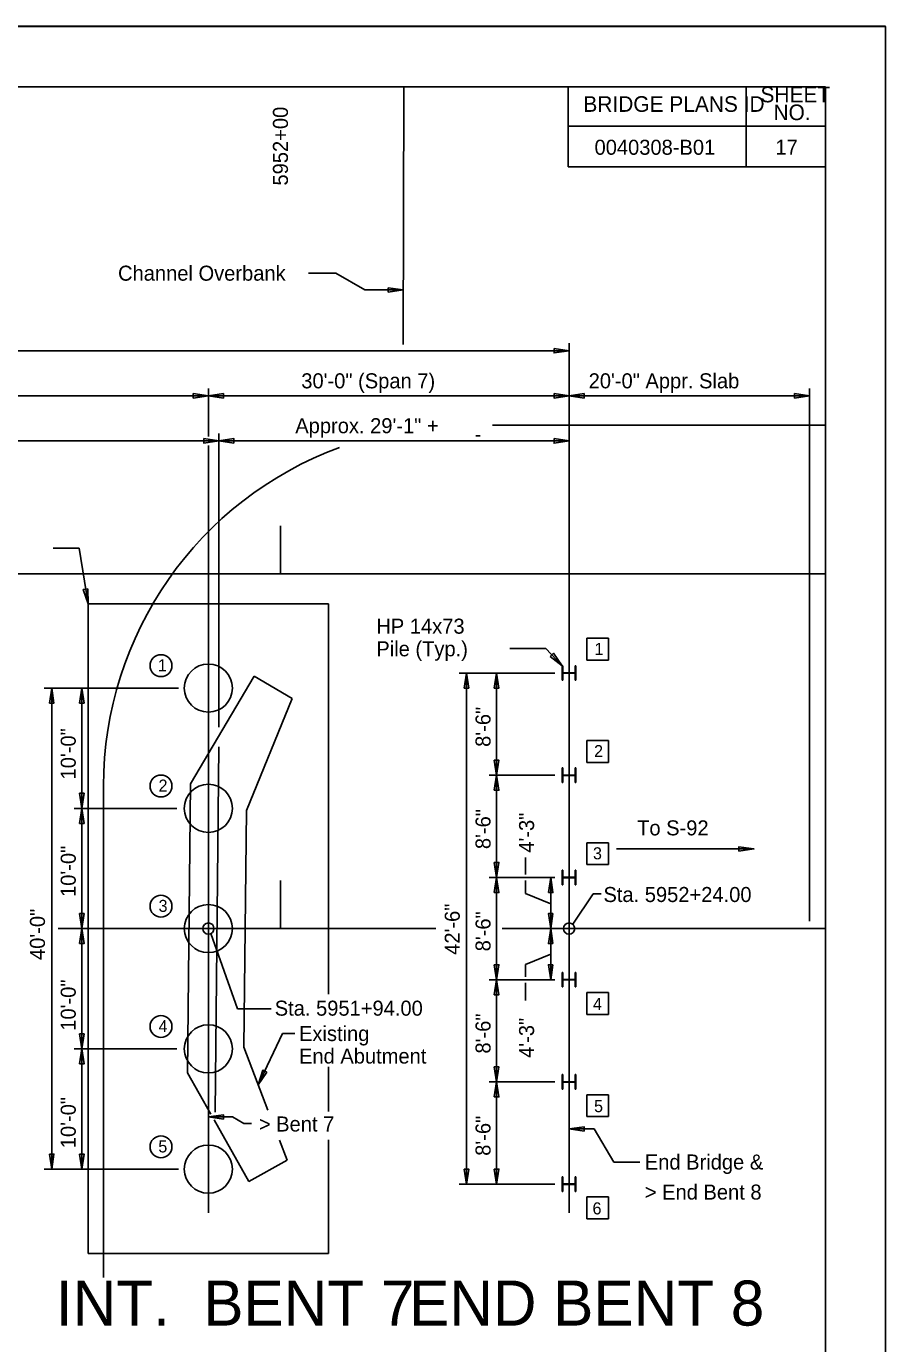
# Model space of a CAD drawing. Extents: x -10371 to -10009, y 1939 to 2167.
# Drawn here: x -10082 to -10010.6, y 2050 to 2159.5 of the extents above; entities that cross this region are included whole.
import ezdxf

# ---------------------------------------------------------------- set-up
doc = ezdxf.new("R2010")
doc.units = 0
for name, color, linetype in [('BR_AUTO DIMENSION', 7, 'Continuous'), ('BR_BORDER LINES', 7, 'Continuous'), ('BR_CENTER LINES', 7, 'Continuous'), ('BR_CONCRETE', 7, 'Continuous'), ('BR_GROUND LINES', 7, 'Continuous'), ('BR_STRUCTURAL STEEL', 7, 'Continuous'), ('BR_TABLE LINES', 7, 'Continuous'), ('BR_TEXT', 7, 'Continuous'), ('RD_SHT_IplotShp', 7, 'Continuous')]:
    doc.layers.add(name, color=color, linetype=linetype)

# ---------------------------------------------------------------- blocks, each defined once
blk = doc.blocks.new('B')
at = {"layer": 'BR_AUTO DIMENSION'}
blk.add_lwpolyline([(-0.2, 0.03), (0, 0), (-0.2, -0.03)], close=True, dxfattribs=at)
blk = doc.blocks.new('ARROW')
at = {"layer": 'BR_AUTO DIMENSION', "xscale": 0.625, "yscale": 0.625}
blk.add_blockref('B', (0, 0), dxfattribs=at)

msp = doc.modelspace()

# ---------------------------------------------------------------- linework, layer by layer
at = {"layer": 'BR_AUTO DIMENSION'}
for p, q in [((-10056.31, 2138.99), (-10058.58, 2138.99)), ((-10053.9, 2137.6), (-10056.31, 2138.99)), ((-10050.7, 2137.6), (-10053.9, 2137.6)), ((-10330.91, 2132.54), (-10036.91, 2132.54)), ((-10016.91, 2085.12), (-10016.91, 2129.41)), ((-10350.91, 2128.79), (-10016.91, 2128.79)), ((-10330.91, 2125.04), (-10036.91, 2125.04)), ((-10079.81, 2116.13), (-10077.66, 2116.13)), ((-10076.91, 2111.49), (-10077.66, 2116.13)), ((-10038.84, 2107.79), (-10041.84, 2107.79)), ((-10037.48, 2106.35), (-10038.84, 2107.79)), ((-10038.1, 2105.74), (-10046.06, 2105.74)), ((-10045.44, 2105.74), (-10045.44, 2063.24)), ((-10042.94, 2105.74), (-10042.94, 2105.74)), ((-10042.94, 2105.74), (-10042.94, 2063.24)), ((-10069.4, 2104.49), (-10080.56, 2104.49)), ((-10079.94, 2104.49), (-10079.94, 2064.49)), ((-10077.44, 2104.49), (-10077.44, 2104.49)), ((-10077.44, 2104.49), (-10077.44, 2064.49)), ((-10038.1, 2097.24), (-10043.56, 2097.24)), ((-10069.54, 2094.49), (-10078.06, 2094.49)), ((-10021.54, 2091.11), (-10032.97, 2091.11)), ((-10040.54, 2090.41), (-10040.54, 2088.99)), ((-10038.1, 2088.74), (-10043.56, 2088.74)), ((-10038.44, 2088.74), (-10038.44, 2080.24)), ((-10040.54, 2088.49), (-10040.54, 2087.41)), ((-10040.54, 2087.41), (-10038.44, 2086.54)), ((-10066.7, 2084.07), (-10064.48, 2077.83)), ((-10040.54, 2081.51), (-10038.44, 2082.37)), ((-10040.54, 2081.51), (-10040.54, 2080.49)), ((-10038.1, 2080.24), (-10043.56, 2080.24)), ((-10040.54, 2079.99), (-10040.54, 2078.5)), ((-10064.48, 2077.83), (-10061.69, 2077.83)), ((-10062.76, 2071.51), (-10060.73, 2075.76)), ((-10060.73, 2075.76), (-10059.71, 2075.76)), ((-10069.54, 2074.49), (-10078.06, 2074.49)), ((-10038.1, 2071.74), (-10043.56, 2071.74)), ((-10066.91, 2068.83), (-10064.91, 2068.83)), ((-10064.91, 2068.83), (-10063.97, 2068.29)), ((-10063.97, 2068.29), (-10063.32, 2068.29)), ((-10036.91, 2067.83), (-10034.81, 2067.83)), ((-10034.81, 2067.83), (-10033.19, 2065.08)), ((-10033.19, 2065.08), (-10031.03, 2065.08)), ((-10069.4, 2064.49), (-10080.56, 2064.49)), ((-10077.44, 2064.49), (-10077.44, 2064.49)), ((-10038.1, 2063.24), (-10046.06, 2063.24)), ((-10042.94, 2063.24), (-10042.94, 2063.24))]:
    msp.add_line(p, q, dxfattribs=at)
for points in [[(-10051.95, 2137.78), (-10050.7, 2137.6), (-10051.95, 2137.41)], [(-10038.16, 2132.73), (-10036.91, 2132.54), (-10038.16, 2132.35)], [(-10068.16, 2128.98), (-10066.91, 2128.79), (-10068.16, 2128.6)], [(-10065.66, 2128.6), (-10066.91, 2128.79), (-10065.66, 2128.98)], [(-10038.16, 2128.98), (-10036.91, 2128.79), (-10038.16, 2128.6)], [(-10035.66, 2128.6), (-10036.91, 2128.79), (-10035.66, 2128.98)], [(-10018.16, 2128.98), (-10016.91, 2128.79), (-10018.16, 2128.6)], [(-10067.28, 2125.23), (-10066.03, 2125.04), (-10067.28, 2124.85)], [(-10064.78, 2124.85), (-10066.03, 2125.04), (-10064.78, 2125.23)], [(-10038.16, 2125.23), (-10036.91, 2125.04), (-10038.16, 2124.85)], [(-10038.48, 2107.12), (-10037.48, 2106.35), (-10038.21, 2107.38)], [(-10045.63, 2104.49), (-10045.44, 2105.74), (-10045.25, 2104.49)], [(-10043.13, 2104.49), (-10042.94, 2105.74), (-10042.75, 2104.49)], [(-10080.13, 2103.24), (-10079.94, 2104.49), (-10079.75, 2103.24)], [(-10077.63, 2103.24), (-10077.44, 2104.49), (-10077.25, 2103.24)], [(-10043.13, 2098.49), (-10042.94, 2097.24), (-10042.75, 2098.49)], [(-10043.13, 2095.99), (-10042.94, 2097.24), (-10042.75, 2095.99)], [(-10077.63, 2095.74), (-10077.44, 2094.49), (-10077.25, 2095.74)], [(-10077.63, 2093.24), (-10077.44, 2094.49), (-10077.25, 2093.24)], [(-10022.79, 2090.92), (-10021.54, 2091.11), (-10022.79, 2091.3)], [(-10043.13, 2089.99), (-10042.94, 2088.74), (-10042.75, 2089.99)], [(-10043.13, 2087.49), (-10042.94, 2088.74), (-10042.75, 2087.49)], [(-10038.63, 2087.49), (-10038.44, 2088.74), (-10038.25, 2087.49)], [(-10077.63, 2085.74), (-10077.44, 2084.49), (-10077.25, 2085.74)], [(-10038.25, 2085.74), (-10038.44, 2084.49), (-10038.63, 2085.74)], [(-10077.63, 2083.24), (-10077.44, 2084.49), (-10077.25, 2083.24)], [(-10038.25, 2083.24), (-10038.44, 2084.49), (-10038.63, 2083.24)], [(-10043.13, 2081.49), (-10042.94, 2080.24), (-10042.75, 2081.49)], [(-10038.25, 2081.49), (-10038.44, 2080.24), (-10038.63, 2081.49)], [(-10043.13, 2078.99), (-10042.94, 2080.24), (-10042.75, 2078.99)], [(-10077.63, 2075.74), (-10077.44, 2074.49), (-10077.25, 2075.74)], [(-10077.63, 2073.24), (-10077.44, 2074.49), (-10077.25, 2073.24)], [(-10062.04, 2072.55), (-10062.76, 2071.51), (-10062.38, 2072.71)], [(-10043.13, 2072.99), (-10042.94, 2071.74), (-10042.75, 2072.99)], [(-10043.13, 2070.49), (-10042.94, 2071.74), (-10042.75, 2070.49)], [(-10065.66, 2068.65), (-10066.91, 2068.83), (-10065.66, 2069.02)], [(-10035.66, 2067.65), (-10036.91, 2067.83), (-10035.66, 2068.02)], [(-10080.13, 2065.74), (-10079.94, 2064.49), (-10079.75, 2065.74)], [(-10077.63, 2065.74), (-10077.44, 2064.49), (-10077.25, 2065.74)], [(-10045.63, 2064.49), (-10045.44, 2063.24), (-10045.25, 2064.49)], [(-10043.13, 2064.49), (-10042.94, 2063.24), (-10042.75, 2064.49)]]:
    msp.add_lwpolyline(points, close=True, dxfattribs=at)
msp.add_lwpolyline([(-10036.6, 2084.85), (-10034.9, 2087.38), (-10034.25, 2087.38)], dxfattribs=at)
for centre in [(-10066.91, 2084.49), (-10036.91, 2084.49)]:
    msp.add_circle(centre, 0.469, dxfattribs=at)
at = {"layer": 'BR_BORDER LINES'}
for p, q in [((-10370.58, 2159.51), (-10010.58, 2159.51)), ((-10015.58, 2154.49), (-10352.25, 2154.49)), ((-10036.98, 2147.83), (-10036.98, 2154.49)), ((-10023.92, 2154.49), (-10023.92, 2154.49)), ((-10022.18, 2147.83), (-10022.18, 2154.49)), ((-10019.76, 2154.49), (-10019.76, 2154.49)), ((-10015.58, 1944.49), (-10015.58, 2154.49)), ((-10036.98, 2151.2), (-10015.58, 2151.2)), ((-10015.58, 2147.83), (-10036.98, 2147.83))]:
    msp.add_line(p, q, dxfattribs=at)
at = {"layer": 'BR_CENTER LINES'}
for p, q in [((-10036.91, 2060.87), (-10036.91, 2133.16)), ((-10066.91, 2125.41), (-10066.91, 2129.41)), ((-10066.91, 2060.87), (-10066.91, 2124.66)), ((-10060.91, 2113.99), (-10060.91, 2117.99)), ((-10352.25, 2113.99), (-10015.58, 2113.99)), ((-10060.91, 2084.49), (-10060.91, 2088.49)), ((-10079.4, 2084.49), (-10047.99, 2084.49)), ((-10042.48, 2084.49), (-10015.58, 2084.49))]:
    msp.add_line(p, q, dxfattribs=at)
at = {"layer": 'BR_CONCRETE'}
for p, q in [((-10068.39, 2096.54), (-10063.1, 2105.48)), ((-10059.95, 2103.61), (-10063.1, 2105.48)), ((-10063.75, 2094.3), (-10059.95, 2103.61)), ((-10068.39, 2096.54), (-10068.65, 2072.5)), ((-10063.75, 2094.3), (-10063.96, 2074.64)), ((-10063.96, 2074.64), (-10061.95, 2069.4)), ((-10068.65, 2072.5), (-10066.71, 2069.05)), ((-10066.44, 2068.58), (-10063.55, 2063.45)), ((-10060.99, 2066.9), (-10060.35, 2065.24)), ((-10060.35, 2065.24), (-10063.55, 2063.45))]:
    msp.add_line(p, q, dxfattribs=at)
for centre in [(-10066.91, 2104.49), (-10066.91, 2094.49), (-10066.91, 2084.49), (-10066.91, 2074.49), (-10066.91, 2064.49)]:
    msp.add_circle(centre, 2, dxfattribs=at)
at = {"layer": 'BR_GROUND LINES'}
for p, q in [((-10043.29, 2126.35), (-10015.58, 2126.35)), ((-10075.63, 2096.35), (-10075.63, 2055.47))]:
    msp.add_line(p, q, dxfattribs=at)
msp.add_arc((-10045.63, 2096.35), 30, 110.2124, 180, dxfattribs=at)
at = {"layer": 'BR_STRUCTURAL STEEL'}
for p, q in [((-10037.48, 2105.14), (-10037.48, 2106.35)), ((-10037.48, 2106.35), (-10037.44, 2106.35)), ((-10037.44, 2106.35), (-10037.44, 2105.82)), ((-10036.39, 2105.82), (-10036.39, 2106.35)), ((-10036.39, 2106.35), (-10036.34, 2106.35)), ((-10036.34, 2106.35), (-10036.34, 2105.14)), ((-10037.44, 2105.14), (-10037.48, 2105.14)), ((-10037.44, 2105.67), (-10037.44, 2105.14)), ((-10037.38, 2105.76), (-10036.44, 2105.76)), ((-10036.44, 2105.72), (-10037.38, 2105.72)), ((-10036.39, 2105.14), (-10036.39, 2105.67)), ((-10036.34, 2105.14), (-10036.39, 2105.14)), ((-10037.48, 2096.64), (-10037.48, 2097.85)), ((-10037.48, 2097.85), (-10037.44, 2097.85)), ((-10037.44, 2097.85), (-10037.44, 2097.32)), ((-10036.39, 2097.32), (-10036.39, 2097.85)), ((-10036.39, 2097.85), (-10036.34, 2097.85)), ((-10036.34, 2097.85), (-10036.34, 2096.64)), ((-10037.44, 2096.64), (-10037.48, 2096.64)), ((-10037.44, 2097.17), (-10037.44, 2096.64)), ((-10037.38, 2097.26), (-10036.44, 2097.26)), ((-10036.44, 2097.22), (-10037.38, 2097.22)), ((-10036.39, 2096.64), (-10036.39, 2097.17)), ((-10036.34, 2096.64), (-10036.39, 2096.64)), ((-10037.48, 2088.14), (-10037.48, 2089.35)), ((-10037.48, 2089.35), (-10037.44, 2089.35)), ((-10037.44, 2089.35), (-10037.44, 2088.82)), ((-10037.38, 2088.76), (-10036.44, 2088.76)), ((-10036.44, 2088.72), (-10037.38, 2088.72)), ((-10036.39, 2088.82), (-10036.39, 2089.35)), ((-10036.39, 2089.35), (-10036.34, 2089.35)), ((-10036.34, 2089.35), (-10036.34, 2088.14)), ((-10037.44, 2088.14), (-10037.48, 2088.14)), ((-10037.44, 2088.67), (-10037.44, 2088.14)), ((-10036.39, 2088.14), (-10036.39, 2088.67)), ((-10036.34, 2088.14), (-10036.39, 2088.14)), ((-10037.48, 2079.64), (-10037.48, 2080.85)), ((-10037.48, 2080.85), (-10037.44, 2080.85)), ((-10037.44, 2080.85), (-10037.44, 2080.32)), ((-10037.44, 2080.17), (-10037.44, 2079.64)), ((-10037.38, 2080.26), (-10036.44, 2080.26)), ((-10036.44, 2080.22), (-10037.38, 2080.22)), ((-10036.39, 2080.32), (-10036.39, 2080.85)), ((-10036.39, 2080.85), (-10036.34, 2080.85)), ((-10036.39, 2079.64), (-10036.39, 2080.17)), ((-10036.34, 2080.85), (-10036.34, 2079.64)), ((-10037.44, 2079.64), (-10037.48, 2079.64)), ((-10036.34, 2079.64), (-10036.39, 2079.64)), ((-10037.48, 2071.14), (-10037.48, 2072.35)), ((-10037.48, 2072.35), (-10037.44, 2072.35)), ((-10037.44, 2072.35), (-10037.44, 2071.82)), ((-10036.39, 2071.82), (-10036.39, 2072.35)), ((-10036.39, 2072.35), (-10036.34, 2072.35)), ((-10036.34, 2072.35), (-10036.34, 2071.14)), ((-10037.44, 2071.67), (-10037.44, 2071.14)), ((-10037.38, 2071.76), (-10036.44, 2071.76)), ((-10036.44, 2071.72), (-10037.38, 2071.72)), ((-10036.39, 2071.14), (-10036.39, 2071.67)), ((-10037.44, 2071.14), (-10037.48, 2071.14)), ((-10036.34, 2071.14), (-10036.39, 2071.14)), ((-10037.48, 2062.64), (-10037.48, 2063.85)), ((-10037.48, 2063.85), (-10037.44, 2063.85)), ((-10037.44, 2063.85), (-10037.44, 2063.32)), ((-10036.39, 2063.32), (-10036.39, 2063.85)), ((-10036.39, 2063.85), (-10036.34, 2063.85)), ((-10036.34, 2063.85), (-10036.34, 2062.64)), ((-10037.44, 2062.64), (-10037.48, 2062.64)), ((-10037.44, 2063.17), (-10037.44, 2062.64)), ((-10037.38, 2063.26), (-10036.44, 2063.26)), ((-10036.44, 2063.22), (-10037.38, 2063.22)), ((-10036.39, 2062.64), (-10036.39, 2063.17)), ((-10036.34, 2062.64), (-10036.39, 2062.64))]:
    msp.add_line(p, q, dxfattribs=at)
for centre, start, end in [((-10037.38, 2105.82), 180, 270), ((-10037.38, 2105.67), 90, 180), ((-10036.44, 2105.82), 270, 360), ((-10036.44, 2105.67), 0, 90), ((-10037.38, 2097.32), 180, 270), ((-10037.38, 2097.17), 90, 180), ((-10036.44, 2097.32), 270, 360), ((-10036.44, 2097.17), 0, 90), ((-10037.38, 2088.82), 180, 270), ((-10037.38, 2088.67), 90, 180), ((-10036.44, 2088.82), 270, 360), ((-10036.44, 2088.67), 0, 90), ((-10037.38, 2080.32), 180, 270), ((-10037.38, 2080.17), 90, 180), ((-10036.44, 2080.32), 270, 360), ((-10036.44, 2080.17), 0, 90), ((-10037.38, 2071.82), 180, 270), ((-10037.38, 2071.67), 90, 180), ((-10036.44, 2071.82), 270, 360), ((-10036.44, 2071.67), 0, 90), ((-10037.38, 2063.32), 180, 270), ((-10037.38, 2063.17), 90, 180), ((-10036.44, 2063.32), 270, 360), ((-10036.44, 2063.17), 0, 90)]:
    msp.add_arc(centre, 0.0569, start, end, dxfattribs=at)
at = {"layer": 'BR_TABLE LINES'}
for p, q in [((-10066.03, 2101.24), (-10066.03, 2125.66)), ((-10076.91, 2057.49), (-10076.91, 2111.49)), ((-10076.91, 2111.49), (-10056.91, 2111.49)), ((-10056.91, 2079.04), (-10056.91, 2111.49)), ((-10066.03, 2099.61), (-10066.35, 2069.23)), ((-10056.91, 2069.29), (-10056.91, 2073.01)), ((-10056.91, 2057.49), (-10056.91, 2066.94)), ((-10076.91, 2057.49), (-10056.91, 2057.49))]:
    msp.add_line(p, q, dxfattribs=at)
at = {"layer": 'BR_TEXT'}
for p, q in [((-10035.44, 2108.63), (-10035.44, 2106.81)), ((-10035.44, 2108.63), (-10033.62, 2108.63)), ((-10033.62, 2108.63), (-10033.62, 2106.81)), ((-10033.62, 2106.81), (-10035.44, 2106.81)), ((-10035.44, 2100.13), (-10035.44, 2098.31)), ((-10035.44, 2100.13), (-10033.62, 2100.13)), ((-10033.62, 2100.13), (-10033.62, 2098.31)), ((-10033.62, 2098.31), (-10035.44, 2098.31)), ((-10035.44, 2091.63), (-10033.62, 2091.63)), ((-10035.44, 2091.63), (-10035.44, 2089.81)), ((-10033.62, 2091.63), (-10033.62, 2089.81)), ((-10033.62, 2089.81), (-10035.44, 2089.81)), ((-10035.44, 2077.36), (-10035.44, 2079.18)), ((-10033.62, 2079.18), (-10035.44, 2079.18)), ((-10033.62, 2077.36), (-10033.62, 2079.18)), ((-10035.44, 2077.36), (-10033.62, 2077.36)), ((-10035.44, 2068.86), (-10035.44, 2070.68)), ((-10033.62, 2070.68), (-10035.44, 2070.68)), ((-10033.62, 2068.86), (-10033.62, 2070.68)), ((-10035.44, 2068.86), (-10033.62, 2068.86)), ((-10035.44, 2060.36), (-10035.44, 2062.18)), ((-10033.62, 2062.18), (-10035.44, 2062.18)), ((-10033.62, 2060.36), (-10033.62, 2062.18)), ((-10035.44, 2060.36), (-10033.62, 2060.36))]:
    msp.add_line(p, q, dxfattribs=at)
msp.add_lwpolyline([(-10050.71, 2133.06), (-10050.64, 2154.49)], dxfattribs=at)
for centre in [(-10070.85, 2106.35), (-10070.85, 2096.35), (-10070.85, 2086.35), (-10070.85, 2076.35), (-10070.85, 2066.35)]:
    msp.add_circle(centre, 0.91, dxfattribs=at)
at = {"layer": 'RD_SHT_IplotShp'}
msp.add_lwpolyline([(-10370.58, 2159.49), (-10010.58, 2159.49), (-10010.58, 1939.49), (-10370.58, 1939.49)], close=True, dxfattribs=at)

# ---------------------------------------------------------------- block references
at = {"layer": 'BR_AUTO DIMENSION', "xscale": 9.999999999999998, "yscale": 10, "rotation": -79.94867980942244}
msp.add_blockref('ARROW', (-10076.91, 2111.49), dxfattribs=at)

# ---------------------------------------------------------------- texts
at = {"layer": 'BR_AUTO DIMENSION'}
for s, p in [('30\'-0" (Span 7)', (-10059.18, 2129.41)), ('20\'-0" Appr. Slab', (-10035.28, 2129.41)), ('Approx. 29\'-1" +', (-10059.68, 2125.68)), ('-', (-10044.76, 2124.98)), ('HP 14x73', (-10052.94, 2109.01)), ('Pile (Typ.)', (-10052.94, 2107.13))]:
    msp.add_text(s, height=1.25, dxfattribs=at).set_placement(p)
at = {"layer": 'BR_TEXT'}
for s, height, p in [('SHEET', 1.3, (-10020.99, 2153.19)), ('BRIDGE PLANS ID', 1.3, (-10035.72, 2152.4)), ('NO.', 1.3, (-10019.91, 2151.71)), ('0040308-B01', 1.2498, (-10034.79, 2148.83)), ('17', 1.25, (-10019.75, 2148.83)), ('Channel Overbank', 1.25, (-10074.42, 2138.36)), ('1', 1, (-10034.79, 2107.25)), ('1', 1, (-10071.11, 2105.88)), ('2', 1, (-10034.83, 2098.75)), ('2', 1, (-10071.05, 2095.88)), ('3', 1, (-10034.92, 2090.25)), ('Sta. 5952+24.00', 1.25, (-10034.05, 2086.7)), ('3', 1, (-10071.05, 2085.88)), ('Sta. 5951+94.00', 1.25, (-10061.39, 2077.25)), ('4', 1, (-10034.92, 2077.73)), ('4', 1, (-10071.05, 2075.88)), ('Existing ', 1.25, (-10059.37, 2075.14)), ('End Abutment ', 1.25, (-10059.37, 2073.27)), ('5', 1, (-10034.83, 2069.23)), ('> Bent 7', 1.25, (-10062.71, 2067.62)), ('5', 1, (-10071.07, 2065.88)), ('End Bridge &', 1.25, (-10030.61, 2064.46)), ('> End Bent 8', 1.25, (-10030.61, 2061.96)), ('6', 1, (-10034.96, 2060.73))]:
    msp.add_text(s, height=height, dxfattribs=at).set_placement(p)
for s, height, rotation, p in [('5952+00', 1.25, 90, (-10060.29, 2146.27)), ('8\'-6"', 1.25, 90, (-10043.44, 2099.6)), ('10\'-0"', 1.25, 90, (-10077.94, 2096.89)), ('8\'-6"', 1.25, 90, (-10043.44, 2091.1)), ('4\'-3"', 1.25, 90, (-10039.82, 2090.8)), ('To S-92', 1.25, 360, (-10031.25, 2092.24)), ('10\'-0"', 1.25, 90, (-10077.94, 2087.12)), ('42\'-6"', 1.25, 90, (-10046, 2082.31)), ('40\'-0"', 1.25, 90, (-10080.5, 2081.88)), ('8\'-6"', 1.25, 90, (-10043.44, 2082.6)), ('10\'-0"', 1.25, 90, (-10077.94, 2076)), ('8\'-6"', 1.25, 90, (-10043.44, 2074.1)), ('4\'-3"', 1.25, 90, (-10039.82, 2073.74)), ('10\'-0"', 1.25, 90, (-10077.94, 2066.23)), ('8\'-6"', 1.25, 90, (-10043.44, 2065.6)), ('INT.  BENT 7', 3.75, 360, (-10079.59, 2051.48)), ('END BENT 8', 3.75, 360, (-10050.21, 2051.48))]:
    msp.add_text(s, height=height, rotation=rotation, dxfattribs=at).set_placement(p)

doc.saveas('drawing.dxf')
